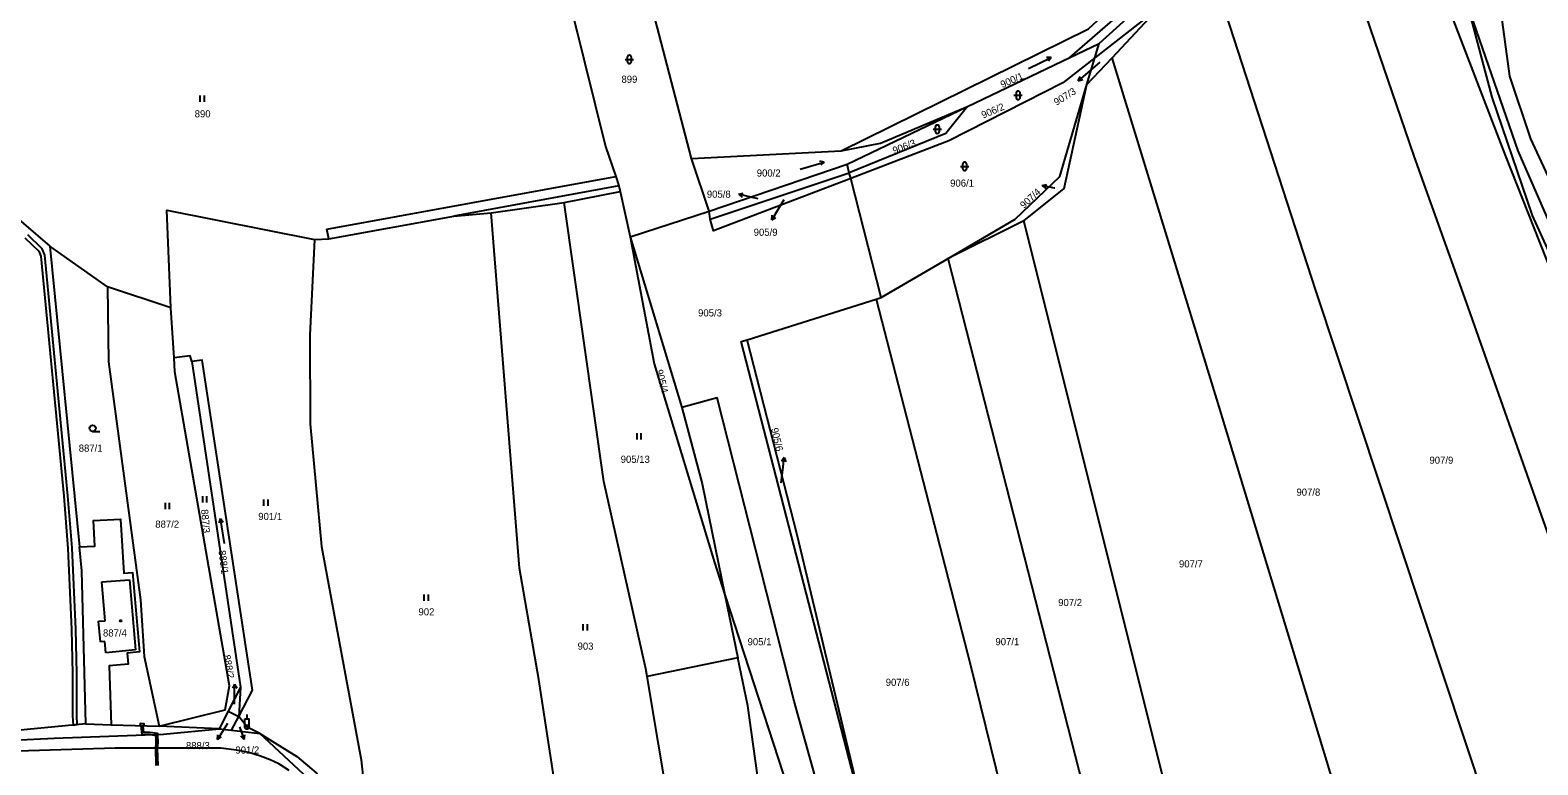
# Model space of a CAD drawing. Extents: x -757266 to -753360, y -1162585 to -1157740.
# Drawn here: x -756589.6 to -756229.8, y -1159271.1 to -1159095.7 of the extents above; entities that cross this region are included whole.
import ezdxf

# ---------------------------------------------------------------- set-up
doc = ezdxf.new("R2010")
doc.units = 0
for name, color, linetype in [('Hranice parcel', 7, 'Continuous'), ('Parcelní čísla', 7, 'Continuous'), ('Pop  PČ popisy', 7, 'Continuous'), ('Poz předměty', 7, 'Continuous'), ('Vnitřní kresba', 7, 'Continuous'), ('Věcná břemena k části', 7, 'Continuous'), ('Značky budov', 7, 'Continuous'), ('Značky kultur', 7, 'Continuous')]:
    doc.layers.add(name, color=color, linetype=linetype)

msp = doc.modelspace()

# ---------------------------------------------------------------- linework, layer by layer
at = {"layer": 'Hranice parcel'}
for p, q in [((-756431.76, -1159126.38), (-756448.68, -1159061.66)), ((-756320.22, -1159090.39), (-756335.52, -1159102.37)), ((-756331.42, -1159102.34), (-756320.22, -1159090.39)), ((-756341.46, -1159102.24), (-756334.5, -1159098.91)), ((-756335.52, -1159102.37), (-756334.5, -1159098.91)), ((-756365.94, -1159113.96), (-756341.46, -1159102.24)), ((-756337.41, -1159108.73), (-756331.42, -1159102.34)), ((-756337.41, -1159108.73), (-756335.52, -1159102.37)), ((-756394.64, -1159127.71), (-756365.94, -1159113.96)), ((-756431.76, -1159126.38), (-756396.08, -1159124.57)), ((-756427.53, -1159138.98), (-756431.76, -1159126.38)), ((-756427.53, -1159138.98), (-756394.64, -1159127.71)), ((-756394.11, -1159129.77), (-756394.64, -1159127.71)), ((-756427.34, -1159140.86), (-756394.11, -1159129.77)), ((-756393.76, -1159131.12), (-756394.11, -1159129.77)), ((-756386.48, -1159159.55), (-756393.76, -1159131.12)), ((-756462.14, -1159136.85), (-756448.78, -1159134.26)), ((-756448.78, -1159134.26), (-756446.37, -1159145.1)), ((-756488.49, -1159140.12), (-756479.57, -1159139.35)), ((-756479.57, -1159139.35), (-756462.14, -1159136.85)), ((-756446.37, -1159145.1), (-756427.53, -1159138.98)), ((-756427.34, -1159140.86), (-756427.53, -1159138.98)), ((-756518.32, -1159145.59), (-756488.49, -1159140.12)), ((-756352.5, -1159141.22), (-756370.56, -1159150.21)), ((-756308.9, -1159315.27), (-756352.5, -1159141.22)), ((-756521.72, -1159145.73), (-756518.32, -1159145.59)), ((-756446.37, -1159145.1), (-756434.09, -1159185.8)), ((-756571.07, -1159156.98), (-756584.84, -1159147.34)), ((-756584.84, -1159147.34), (-756577.77, -1159219.1)), ((-756386.48, -1159159.55), (-756370.56, -1159150.21)), ((-756326.93, -1159320.64), (-756370.56, -1159150.21)), ((-756555.98, -1159162.01), (-756571.07, -1159156.98)), ((-756418.52, -1159169.69), (-756387.7, -1159159.94)), ((-756387.7, -1159159.94), (-756386.48, -1159159.55)), ((-756555.22, -1159173.95), (-756555.98, -1159162.01)), ((-756551.01, -1159174.85), (-756539.34, -1159252.57)), ((-756423.78, -1159230.53), (-756420.7, -1159245.53)), ((-756420.7, -1159245.53), (-756442.34, -1159249.98)), ((-756539.34, -1159252.57), (-756542.33, -1159258.32)), ((-756539.34, -1159252.57), (-756539.79, -1159259.58)), ((-756542.33, -1159258.32), (-756544.49, -1159262.48)), ((-756542.33, -1159258.32), (-756539.79, -1159259.58)), ((-756576.31, -1159261.31), (-756604.79, -1159264.09)), ((-756576.31, -1159261.31), (-756570.19, -1159261.52)), ((-756570.19, -1159261.52), (-756558.74, -1159261.9)), ((-756544.49, -1159262.48), (-756558.74, -1159261.9)), ((-756541.48, -1159262.83), (-756539.79, -1159259.58)), ((-756537.81, -1159262.11), (-756539.79, -1159259.58)), ((-756534.74, -1159263.62), (-756537.81, -1159262.11)), ((-756544.49, -1159262.48), (-756541.48, -1159262.83)), ((-756541.48, -1159262.83), (-756534.74, -1159263.62))]:
    msp.add_line(p, q, dxfattribs=at)
for points in [[(-756396.08, -1159124.57), (-756337.01, -1159095.45), (-756314.45, -1159074.45), (-756291.2, -1159047.77), (-756263.17, -1159009.1)], [(-756341.46, -1159102.24), (-756320.38, -1159083.88), (-756293.63, -1159056.67), (-756260.29, -1159012.64)], [(-756334.5, -1159098.91), (-756310.67, -1159077.33), (-756287.1, -1159051.11), (-756260.29, -1159012.64)], [(-756191.02, -1159228.39), (-756221.05, -1159167.3), (-756237.43, -1159125.82), (-756251.62, -1159088.97), (-756255.44, -1159034.2)], [(-756245.53, -1159041.1), (-756236.62, -1159106.75), (-756231.59, -1159121.7), (-756207.52, -1159173.66), (-756187.58, -1159218.54), (-756167.07, -1159263.16), (-756159.77, -1159272), (-756149.59, -1159280.27), (-756138.25, -1159286.97), (-756122.88, -1159294.3)], [(-756210.61, -1159263.61), (-756246.83, -1159160.75), (-756259.35, -1159125.84), (-756284.41, -1159052.51)], [(-756466.67, -1159067.97), (-756459.79, -1159093.4), (-756452.26, -1159123.5), (-756449.85, -1159130.66), (-756449.08, -1159132.93), (-756448.78, -1159134.26)], [(-756237.05, -1159295.88), (-756282.77, -1159157.88), (-756308.19, -1159079.63)], [(-756246.64, -1159089.86), (-756240.84, -1159111.78), (-756231.2, -1159139.95), (-756191.02, -1159228.39)], [(-756246.64, -1159089.86), (-756234.58, -1159124.57), (-756216.81, -1159165.34), (-756187.87, -1159223.97), (-756168.21, -1159263.53), (-756161.14, -1159273.52), (-756147.77, -1159283.56), (-756126.42, -1159295.4)], [(-756335.52, -1159102.37), (-756343.13, -1159108.32), (-756370.34, -1159122.19), (-756393.76, -1159131.12)], [(-756270.05, -1159303.48), (-756306.39, -1159183.85), (-756331.42, -1159102.34)], [(-756370.56, -1159150.21), (-756354.57, -1159140.83), (-756343.9, -1159130.68), (-756337.41, -1159108.73)], [(-756352.5, -1159141.22), (-756342.88, -1159133.56), (-756337.41, -1159108.73)], [(-756396.08, -1159124.57), (-756386.66, -1159122.71), (-756365.94, -1159113.96)], [(-756365.94, -1159113.96), (-756371.11, -1159120.44), (-756394.11, -1159129.77)], [(-756613.88, -1159126.79), (-756597.48, -1159136.48), (-756584.84, -1159147.34)], [(-756393.76, -1159131.12), (-756426.53, -1159143.62), (-756427.34, -1159140.86)], [(-756555.98, -1159162.01), (-756556.92, -1159138.71), (-756521.72, -1159145.73)], [(-756456.32, -1159343.49), (-756458.35, -1159326.17), (-756460.69, -1159299.41), (-756468.18, -1159250.75), (-756472.78, -1159224.14), (-756479.57, -1159139.35)], [(-756442.34, -1159249.98), (-756442.64, -1159248.15), (-756452.66, -1159203.49), (-756462.14, -1159136.85)], [(-756521.72, -1159145.73), (-756522.81, -1159168.58), (-756522.73, -1159189.71), (-756520.08, -1159218.98), (-756510.6, -1159269.92), (-756504.65, -1159325.98)], [(-756446.37, -1159145.1), (-756440.66, -1159175.35), (-756426.29, -1159222.81), (-756423.78, -1159230.53)], [(-756571.07, -1159156.98), (-756570.83, -1159174.93), (-756563.2, -1159231.71), (-756562.39, -1159245.23), (-756558.74, -1159261.9)], [(-756387.7, -1159159.94), (-756365.31, -1159247.02), (-756345.76, -1159326.26)], [(-756389.4, -1159288.21), (-756419.88, -1159170.06), (-756418.52, -1159169.69)], [(-756389.4, -1159288.21), (-756406.59, -1159216.21), (-756418.52, -1159169.69)], [(-756558.74, -1159261.9), (-756543, -1159257.99), (-756542.02, -1159252.21), (-756555, -1159177.33), (-756555.22, -1159173.95)], [(-756551.01, -1159174.85), (-756551.34, -1159173.47), (-756555.22, -1159173.95)], [(-756539.79, -1159259.58), (-756536.53, -1159253.31), (-756548.51, -1159174.52), (-756551.01, -1159174.85)], [(-756384.87, -1159338.04), (-756387.79, -1159325.8), (-756407.24, -1159255.88), (-756425.67, -1159183.52), (-756434.09, -1159185.8)], [(-756434.09, -1159185.8), (-756429.23, -1159204.03), (-756423.78, -1159230.53)], [(-756577.77, -1159219.1), (-756574.15, -1159218.9), (-756574.42, -1159212.76), (-756567.98, -1159212.49), (-756567.18, -1159225.33), (-756565.11, -1159225.19), (-756563.5, -1159244.14), (-756566.42, -1159244.44), (-756566.18, -1159247.04), (-756570.68, -1159247.46), (-756570.19, -1159261.52)], [(-756576.31, -1159261.31), (-756577.21, -1159224.8), (-756577.77, -1159219.1)], [(-756423.78, -1159230.53), (-756404.19, -1159290.84), (-756399.98, -1159341.26)], [(-756404.64, -1159342.26), (-756413.39, -1159292.41), (-756418.34, -1159257), (-756420.7, -1159245.53)], [(-756425.7, -1159344.98), (-756431.28, -1159308.39), (-756434.25, -1159298.46), (-756442.34, -1159249.98)], [(-756648.81, -1159268.27), (-756629.06, -1159266.77), (-756604.92, -1159265.75), (-756583.8, -1159264.75), (-756557.72, -1159263.78), (-756544.49, -1159262.48)], [(-756504.65, -1159325.98), (-756507.74, -1159322.44), (-756510.32, -1159313.24), (-756512.54, -1159298.77), (-756516.6, -1159287.38), (-756522.03, -1159275.44), (-756534.74, -1159263.62)], [(-756534.74, -1159263.62), (-756525.9, -1159269.14), (-756521.33, -1159273), (-756518.25, -1159278.57), (-756512.56, -1159292.48), (-756508.71, -1159308.22), (-756504.65, -1159325.98)]]:
    msp.add_lwpolyline(points, dxfattribs=at)
at = {"layer": 'Pop  PČ popisy'}
for p, q in [((-756334.37, -1159103.36), (-756337.23, -1159105.86)), ((-756337.23, -1159105.86), (-756339.495, -1159107.829)), ((-756339.495, -1159107.829), (-756339.068, -1159106.794)), ((-756339.495, -1159107.829), (-756338.411, -1159107.55)), ((-756348.076, -1159132.857), (-756346.997, -1159132.557)), ((-756420.492, -1159134.884), (-756419.399, -1159134.64)), ((-756417.58, -1159135.61), (-756420.492, -1159134.884)), ((-756420.492, -1159134.884), (-756419.641, -1159135.612)), ((-756415.89, -1159136.02), (-756417.58, -1159135.61)), ((-756409.7, -1159136.21), (-756411.05, -1159138.48)), ((-756345.13, -1159133.43), (-756348.076, -1159132.857)), ((-756348.076, -1159132.857), (-756347.188, -1159133.54)), ((-756345.08, -1159133.44), (-756345.13, -1159133.43)), ((-756411.05, -1159138.48), (-756412.596, -1159141.052)), ((-756412.596, -1159141.052), (-756412.509, -1159139.936)), ((-756412.596, -1159141.052), (-756411.651, -1159140.452)), ((-756410.34, -1159203.82), (-756410, -1159200.71)), ((-756409.686, -1159197.725), (-756410.289, -1159198.669)), ((-756410, -1159200.71), (-756409.686, -1159197.725)), ((-756409.686, -1159197.725), (-756409.293, -1159198.774)), ((-756540.77, -1159251.839), (-756541.271, -1159252.84)), ((-756540.77, -1159254.84), (-756540.77, -1159251.839)), ((-756540.77, -1159251.839), (-756540.269, -1159252.84)), ((-756540.77, -1159256.6), (-756540.77, -1159254.84)), ((-756542.44, -1159261.24), (-756543.25, -1159262.5)), ((-756539.62, -1159262.02), (-756539.54, -1159262.23)), ((-756543.25, -1159262.5), (-756544.884, -1159265.017)), ((-756544.884, -1159265.017), (-756544.759, -1159263.904)), ((-756544.884, -1159265.017), (-756543.919, -1159264.45)), ((-756539.54, -1159262.23), (-756538.465, -1159265.032)), ((-756538.465, -1159265.032), (-756539.291, -1159264.276)), ((-756538.465, -1159265.032), (-756538.356, -1159263.917))]:
    msp.add_line(p, q, dxfattribs=at)
at = {"layer": 'Poz předměty'}
for p, q in [((-756538.31, -1159260.106), (-756537.31, -1159260.106)), ((-756538.31, -1159262.106), (-756538.31, -1159260.106)), ((-756537.81, -1159260.106), (-756537.81, -1159259.106)), ((-756537.31, -1159262.106), (-756537.31, -1159260.106))]:
    msp.add_line(p, q, dxfattribs=at)
for radius in [0.5, 0.0303]:
    msp.add_circle((-756537.81, -1159262.1076), radius, dxfattribs=at)
at = {"layer": 'Vnitřní kresba'}
for p, q in [((-756518.77, -1159143.25), (-756449.85, -1159130.66)), ((-756449.08, -1159132.93), (-756488.49, -1159140.12)), ((-756518.32, -1159145.59), (-756518.77, -1159143.25)), ((-756572.43, -1159227.46), (-756565.84, -1159226.91)), ((-756571.62, -1159236.73), (-756572.43, -1159227.46)), ((-756565.84, -1159226.91), (-756564.4, -1159243.63)), ((-756573.22, -1159236.84), (-756571.62, -1159236.73)), ((-756572.81, -1159241.77), (-756573.22, -1159236.84)), ((-756571.75, -1159241.68), (-756572.81, -1159241.77)), ((-756571.47, -1159244.4), (-756571.75, -1159241.68)), ((-756564.4, -1159243.63), (-756571.47, -1159244.4)), ((-756569.27, -1159267.16), (-756611.38, -1159268.45)), ((-756544.04, -1159267.16), (-756569.27, -1159267.16)), ((-756540.32, -1159267.59), (-756544.04, -1159267.16)), ((-756537.38, -1159268.17), (-756540.32, -1159267.59)), ((-756534.59, -1159269.03), (-756537.38, -1159268.17)), ((-756532.27, -1159269.89), (-756534.59, -1159269.03)), ((-756530.26, -1159270.89), (-756532.27, -1159269.89)), ((-756527.78, -1159272.46), (-756530.26, -1159270.89))]:
    msp.add_line(p, q, dxfattribs=at)
at = {"layer": 'Věcná břemena k části'}
for points in [[(-756590.82, -1159145.29), (-756587.52, -1159148.53), (-756587.01, -1159149.72), (-756581.53, -1159206.99), (-756580.54, -1159219.48), (-756579.69, -1159238.78), (-756579.42, -1159249.31), (-756579.44, -1159259.38), (-756579.31, -1159261.6), (-756578.31, -1159261.51), (-756578.44, -1159259.37), (-756578.42, -1159249.29), (-756578.69, -1159238.74), (-756579.55, -1159219.31), (-756580.53, -1159206.9), (-756586.03, -1159149.49), (-756586.68, -1159147.94), (-756590.11, -1159144.59)], [(-756559.04, -1159271.28), (-756559.18, -1159267.16), (-756559.04, -1159265.76), (-756559.09, -1159263.83), (-756559.1, -1159263.62), (-756560.97, -1159263.36), (-756562.44, -1159263.37), (-756562.61, -1159261.77), (-756563.11, -1159261.75), (-756562.88, -1159263.87), (-756560.77, -1159263.89), (-756559.58, -1159264.06), (-756559.54, -1159265.74), (-756559.68, -1159267.16), (-756559.54, -1159271.26)]]:
    msp.add_lwpolyline(points, dxfattribs=at)
msp.add_lwpolyline([(-756563.11, -1159261.75), (-756562.61, -1159261.77), (-756562.36, -1159261.78), (-756562.34, -1159261.28), (-756563.34, -1159261.25), (-756563.36, -1159261.74)], close=True, dxfattribs=at)
at = {"layer": 'Značky budov'}
msp.add_circle((-756567.9568, -1159236.7292), 0.175, dxfattribs=at)
at = {"layer": 'Značky kultur'}
for p, q in [((-756447.591, -1159102.721), (-756445.589, -1159102.721)), ((-756447.091, -1159102.221), (-756447.091, -1159103.222)), ((-756446.089, -1159103.222), (-756446.089, -1159102.221)), ((-756351.337, -1159104.925), (-756345.944, -1159102.295)), ((-756345.944, -1159102.295), (-756347.043, -1159102.273)), ((-756345.944, -1159102.295), (-756346.603, -1159103.174)), ((-756354.331, -1159110.801), (-756354.331, -1159111.802)), ((-756353.329, -1159111.802), (-756353.329, -1159110.801)), ((-756548.981, -1159112.88), (-756548.981, -1159111.38)), ((-756547.98, -1159112.88), (-756547.98, -1159111.38)), ((-756354.831, -1159111.301), (-756352.829, -1159111.301)), ((-756374.121, -1159119.391), (-756372.119, -1159119.391)), ((-756373.621, -1159118.891), (-756373.621, -1159119.892)), ((-756372.619, -1159119.892), (-756372.619, -1159118.891)), ((-756405.845, -1159128.91), (-756400.077, -1159127.257)), ((-756400.077, -1159127.257), (-756401.155, -1159127.044)), ((-756400.077, -1159127.257), (-756400.878, -1159128.008)), ((-756367.581, -1159128.251), (-756365.579, -1159128.251)), ((-756367.081, -1159127.751), (-756367.081, -1159128.752)), ((-756366.079, -1159128.752), (-756366.079, -1159127.751)), ((-756574.663, -1159191.52), (-756572.913, -1159191.52)), ((-756444.751, -1159193.47), (-756444.751, -1159191.97)), ((-756443.75, -1159193.47), (-756443.75, -1159191.97)), ((-756548.391, -1159208.51), (-756548.391, -1159207.01)), ((-756547.39, -1159208.51), (-756547.39, -1159207.01)), ((-756533.801, -1159209.26), (-756533.801, -1159207.76)), ((-756532.8, -1159209.26), (-756532.8, -1159207.76)), ((-756557.271, -1159210.06), (-756557.271, -1159208.56)), ((-756556.27, -1159210.06), (-756556.27, -1159208.56)), ((-756544.164, -1159212.329), (-756544.506, -1159213.372)), ((-756543.225, -1159218.255), (-756544.164, -1159212.329)), ((-756544.164, -1159212.329), (-756543.515, -1159213.215)), ((-756495.551, -1159231.98), (-756495.551, -1159230.48)), ((-756494.55, -1159231.98), (-756494.55, -1159230.48)), ((-756457.591, -1159239.05), (-756457.591, -1159237.55)), ((-756456.59, -1159239.05), (-756456.59, -1159237.55))]:
    msp.add_line(p, q, dxfattribs=at)
msp.add_circle((-756574.6629, -1159190.7698), 0.75, dxfattribs=at)
for centre, start, end in [((-756446.59, -1159102.2209), 0, 180), ((-756446.59, -1159103.2209), 180, 359.987886), ((-756353.83, -1159110.8009), 0, 180), ((-756353.83, -1159111.8009), 180, 359.987886), ((-756373.12, -1159118.8909), 0, 180), ((-756373.12, -1159119.8909), 180, 359.987886), ((-756366.58, -1159127.7509), 0, 180), ((-756366.58, -1159128.7509), 180, 359.987886)]:
    msp.add_arc(centre, 0.5, start, end, dxfattribs=at)

# ---------------------------------------------------------------- texts
at = {"layer": 'Parcelní čísla'}
for s, p in [('899', (-756448.47, -1159108.33)), ('890', (-756550.3, -1159116.56)), ('900/2', (-756416.19, -1159130.7)), ('906/1', (-756370.05, -1159133.1)), ('905/8', (-756428.097, -1159135.75)), ('905/9', (-756416.927, -1159144.828)), ('905/3', (-756430.19, -1159164.08)), ('887/1', (-756577.968, -1159196.36)), ('905/13', (-756448.657, -1159199.02)), ('907/9', (-756255.69, -1159199.23)), ('907/8', (-756287.43, -1159206.86)), ('901/1', (-756535.13, -1159212.66)), ('887/2', (-756559.7, -1159214.5)), ('907/7', (-756315.45, -1159223.98)), ('907/2', (-756344.27, -1159233.19)), ('902', (-756496.9, -1159235.43)), ('887/4', (-756572.178, -1159240.47)), ('903', (-756458.94, -1159243.62)), ('905/1', (-756418.38, -1159242.56)), ('907/1', (-756359.25, -1159242.55)), ('907/6', (-756385.42, -1159252.25)), ('888/3', (-756552.387, -1159267.348)), ('901/2', (-756540.587, -1159268.418))]:
    msp.add_text(s, height=1.7, dxfattribs=at).set_placement(p)
for s, rotation, p in [('900/1', 24, (-756357.594, -1159109.606)), ('907/3', 32, (-756344.675, -1159113.821)), ('906/2', 23, (-756362.167, -1159116.872)), ('906/3', 21, (-756383.385, -1159125.363)), ('907/4', 43, (-756352.435, -1159138.45)), ('905/4', 284, (-756440.284, -1159176.985)), ('905/6', 283, (-756412.798, -1159190.871)), ('887/3', 275, (-756548.776, -1159210.174)), ('888/1', 277, (-756544.603, -1159220.013)), ('888/2', 280, (-756543.487, -1159244.997))]:
    msp.add_text(s, height=1.7, rotation=rotation, dxfattribs=at).set_placement(p)

doc.saveas('drawing.dxf')
